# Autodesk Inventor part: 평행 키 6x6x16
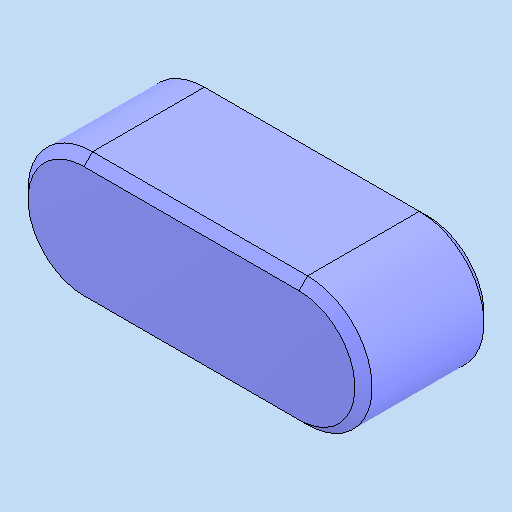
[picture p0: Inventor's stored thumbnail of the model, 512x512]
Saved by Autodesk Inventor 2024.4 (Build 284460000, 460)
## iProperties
Created: 2025-11
Part Number: 평행 키 6x6x16
Material: 강철, 연강
Description: 키 및 해당 키홈
Document SubType Name: Modeling
Designer: home
Density: 7.85 g/cm^3
Appearance: 기본값
Author: jhkim
Sending System: Autodesk Inventor 2026
Preprocessor: ST-DEVELOPER v20.1
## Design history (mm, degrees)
feature "Solid1"
node "솔리드1"
